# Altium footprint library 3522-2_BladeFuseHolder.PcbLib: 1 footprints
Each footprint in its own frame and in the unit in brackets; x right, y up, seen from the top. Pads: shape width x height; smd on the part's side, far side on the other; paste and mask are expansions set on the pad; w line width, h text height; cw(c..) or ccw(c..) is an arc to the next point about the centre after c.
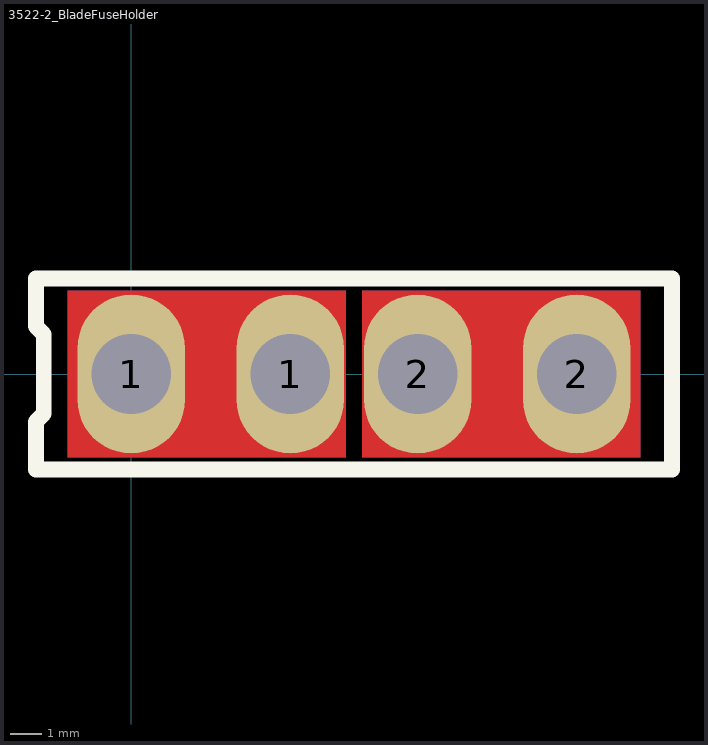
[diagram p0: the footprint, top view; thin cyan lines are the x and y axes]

## 3522-2_BladeFuseHolder [mil]
pads (4):
  oval 135x200 hole 100: 1(0,0) 1(200,0) 2(360,0) 2(560,0)
Top Layer:
  rectangle: 290,-105 640,105
  rectangle: -80,-105 270,105
Bottom Layer:
  rectangle: 290,-105 640,105
  rectangle: -80,-105 270,105
Top Overlay:
  lines w20: -120,-120 680,-120 680,120 -120,120 -120,60 -110,50 -110,-50 -120,-60 -120,-120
